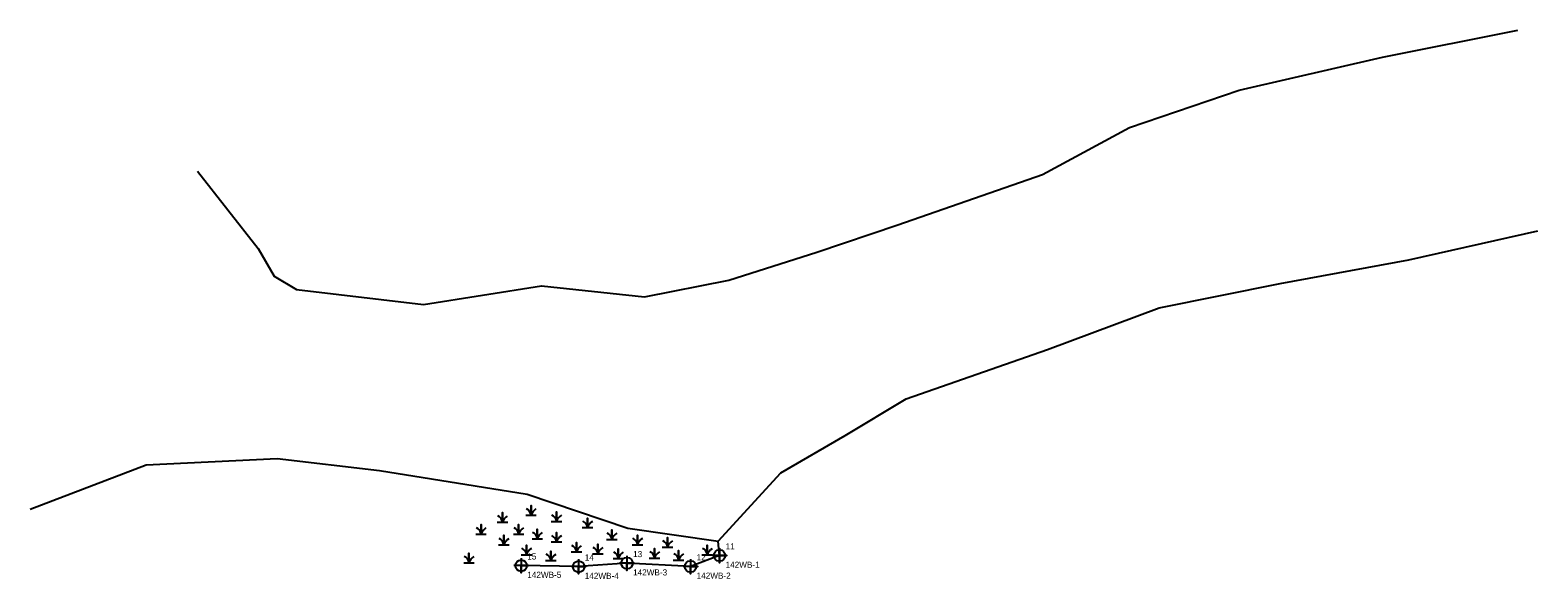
# Model space of a CAD drawing. Extents: x 2110998 to 2111615, y 1005740 to 1005964.
import ezdxf

# ---------------------------------------------------------------- set-up
doc = ezdxf.new("R2010")
doc.units = 0
for name, color, linetype in [('Exist Environmental Wetland Boundary', 7, 'Continuous'), ('Exist Environmental Wetland Boundary Cogo Comment', 7, 'Continuous'), ('Exist Environmental Wetland Boundary Cogo Number', 7, 'Continuous'), ('Exist Environmental Wetland Boundary Cogo Point CELL', 7, 'Continuous'), ('Exist Hydro Jurisdictional Stream or Body of Water Mitigable', 7, 'Continuous'), ('Exist Hydro Swamp or Marsh', 7, 'Continuous')]:
    doc.layers.add(name, color=color, linetype=linetype)

msp = doc.modelspace()

# ---------------------------------------------------------------- linework, layer by layer
at = {"layer": 'Exist Environmental Wetland Boundary'}
msp.add_line((2111279.88, 1005749.38), (2111279.31, 1005755.28), dxfattribs=at)
msp.add_lwpolyline([(2111279.88, 1005749.38), (2111268.04, 1005744.93), (2111242.04, 1005746.25), (2111222.26, 1005744.86), (2111198.75, 1005745.27)], dxfattribs=at)
at = {"layer": 'Exist Environmental Wetland Boundary Cogo Point CELL'}
for points in [[(2111198.75, 1005748.27), (2111198.75, 1005742.27), (2111198.75, 1005745.27), (2111201.75, 1005745.27), (2111195.75, 1005745.27)], [(2111222.26, 1005747.86), (2111222.26, 1005741.86), (2111222.26, 1005744.86), (2111225.26, 1005744.86), (2111219.26, 1005744.86)], [(2111242.04, 1005749.25), (2111242.04, 1005743.25), (2111242.04, 1005746.25), (2111245.04, 1005746.25), (2111239.04, 1005746.25)], [(2111268.04, 1005747.93), (2111268.04, 1005741.93), (2111268.04, 1005744.93), (2111271.04, 1005744.93), (2111265.04, 1005744.93)], [(2111279.88, 1005752.38), (2111279.88, 1005746.38), (2111279.88, 1005749.38), (2111282.88, 1005749.38), (2111276.88, 1005749.38)]]:
    msp.add_lwpolyline(points, dxfattribs=at)
for centre in [(2111242.04, 1005746.25), (2111279.88, 1005749.38), (2111198.75, 1005745.27), (2111222.26, 1005744.86), (2111268.04, 1005744.93)]:
    msp.add_circle(centre, 2.34, dxfattribs=at)
at = {"layer": 'Exist Hydro Jurisdictional Stream or Body of Water Mitigable'}
for points in [[(2111066.33, 1005906.62), (2111091.17, 1005874.98), (2111097.77, 1005863.75), (2111106.81, 1005858.31), (2111158.74, 1005852.11), (2111207.06, 1005859.75), (2111249.26, 1005855.28), (2111283.66, 1005862.06), (2111319.72, 1005873.59), (2111352.86, 1005884.66), (2111412, 1005905.25), (2111447.66, 1005924.6), (2111492.51, 1005939.82), (2111551.13, 1005953.39), (2111606.48, 1005964.38)], [(2110997.88, 1005768.36), (2111045.38, 1005786.58), (2111098.97, 1005789.12), (2111140.82, 1005784.24), (2111201.22, 1005774.47), (2111242.33, 1005760.59), (2111279.31, 1005755.28), (2111304.91, 1005783.21), (2111331.28, 1005798.52), (2111356.24, 1005813.53), (2111414.03, 1005833.75), (2111459.69, 1005850.7), (2111509.19, 1005860.72), (2111561.93, 1005870.46), (2111614.66, 1005882.33)]]:
    msp.add_lwpolyline(points, dxfattribs=at)
at = {"layer": 'Exist Hydro Swamp or Marsh'}
for p, q in [((2111202.8, 1005767.67), (2111202.8, 1005767.67)), ((2111191.08, 1005764.8), (2111191.08, 1005764.8)), ((2111213.19, 1005765.13), (2111213.19, 1005765.13)), ((2111225.89, 1005762.59), (2111225.89, 1005762.59)), ((2111182.35, 1005759.94), (2111182.35, 1005759.94)), ((2111191.64, 1005755.51), (2111191.64, 1005755.51)), ((2111197.71, 1005759.94), (2111197.71, 1005759.94)), ((2111205.34, 1005758.06), (2111205.34, 1005758.06)), ((2111213.19, 1005756.73), (2111213.19, 1005756.73)), ((2111235.84, 1005757.72), (2111235.84, 1005757.72)), ((2111246.34, 1005755.62), (2111246.34, 1005755.62)), ((2111258.61, 1005754.63), (2111258.61, 1005754.63)), ((2111177.38, 1005748.22), (2111177.38, 1005748.22)), ((2111200.92, 1005751.53), (2111200.92, 1005751.53)), ((2111210.86, 1005749.1), (2111210.86, 1005749.1)), ((2111221.36, 1005752.64), (2111221.36, 1005752.64)), ((2111230.09, 1005751.87), (2111230.09, 1005751.87)), ((2111238.49, 1005749.99), (2111238.49, 1005749.99)), ((2111253.3, 1005750.1), (2111253.3, 1005750.1)), ((2111263.14, 1005749.32), (2111263.14, 1005749.32)), ((2111274.85, 1005751.42), (2111274.85, 1005751.42))]:
    msp.add_line(p, q, dxfattribs=at)
for points in [[(2111188.93, 1005763.02), (2111191.08, 1005763.02), (2111191.08, 1005766.96), (2111191.08, 1005763.02), (2111193.23, 1005763.02)], [(2111200.65, 1005765.89), (2111202.8, 1005765.89), (2111202.8, 1005769.84), (2111202.8, 1005765.89), (2111204.95, 1005765.89)], [(2111211.04, 1005763.35), (2111213.19, 1005763.35), (2111213.19, 1005767.29), (2111213.19, 1005763.35), (2111215.34, 1005763.35)], [(2111180.2, 1005758.15), (2111182.35, 1005758.15), (2111182.35, 1005762.1), (2111182.35, 1005758.15), (2111184.5, 1005758.15)], [(2111195.56, 1005758.15), (2111197.71, 1005758.15), (2111197.71, 1005762.1), (2111197.71, 1005758.15), (2111199.86, 1005758.15)], [(2111203.19, 1005756.27), (2111205.34, 1005756.27), (2111205.34, 1005760.22), (2111205.34, 1005756.27), (2111207.49, 1005756.27)], [(2111223.74, 1005760.81), (2111225.89, 1005760.81), (2111225.89, 1005764.75), (2111225.89, 1005760.81), (2111228.05, 1005760.81)], [(2111189.49, 1005753.73), (2111191.64, 1005753.73), (2111191.64, 1005757.68), (2111191.64, 1005753.73), (2111193.79, 1005753.73)], [(2111211.04, 1005754.95), (2111213.19, 1005754.95), (2111213.19, 1005758.89), (2111213.19, 1005754.95), (2111215.34, 1005754.95)], [(2111219.21, 1005750.86), (2111221.36, 1005750.86), (2111221.36, 1005754.8), (2111221.36, 1005750.86), (2111223.51, 1005750.86)], [(2111227.94, 1005750.08), (2111230.09, 1005750.08), (2111230.09, 1005754.03), (2111230.09, 1005750.08), (2111232.24, 1005750.08)], [(2111233.69, 1005755.94), (2111235.84, 1005755.94), (2111235.84, 1005759.89), (2111235.84, 1005755.94), (2111237.99, 1005755.94)], [(2111244.19, 1005753.84), (2111246.34, 1005753.84), (2111246.34, 1005757.79), (2111246.34, 1005753.84), (2111248.49, 1005753.84)], [(2111256.46, 1005752.85), (2111258.61, 1005752.85), (2111258.61, 1005756.79), (2111258.61, 1005752.85), (2111260.76, 1005752.85)], [(2111175.23, 1005746.43), (2111177.38, 1005746.43), (2111177.38, 1005750.38), (2111177.38, 1005746.43), (2111179.53, 1005746.43)], [(2111198.77, 1005749.75), (2111200.92, 1005749.75), (2111200.92, 1005753.7), (2111200.92, 1005749.75), (2111203.07, 1005749.75)], [(2111208.71, 1005747.32), (2111210.87, 1005747.32), (2111210.87, 1005751.26), (2111210.87, 1005747.32), (2111213.02, 1005747.32)], [(2111236.34, 1005748.2), (2111238.49, 1005748.2), (2111238.49, 1005752.15), (2111238.49, 1005748.2), (2111240.64, 1005748.2)], [(2111251.15, 1005748.31), (2111253.3, 1005748.31), (2111253.3, 1005752.26), (2111253.3, 1005748.31), (2111255.45, 1005748.31)], [(2111260.99, 1005747.54), (2111263.14, 1005747.54), (2111263.14, 1005751.48), (2111263.14, 1005747.54), (2111265.29, 1005747.54)], [(2111272.7, 1005749.64), (2111274.85, 1005749.64), (2111274.85, 1005753.59), (2111274.85, 1005749.64), (2111277, 1005749.64)]]:
    msp.add_lwpolyline(points, dxfattribs=at)
for centre, radius, start, end in [((2111199.73, 1005765.67), 3.07, 4.14034, 67.53497), ((2111207.36, 1005764.38), 4.81, 122.12745, 161.62219), ((2111179.29, 1005757.93), 3.07, 4.14034, 67.53497), ((2111186.91, 1005756.64), 4.81, 122.12745, 161.62219), ((2111188.02, 1005762.79), 3.07, 4.14034, 67.53497), ((2111195.64, 1005761.5), 4.81, 122.12745, 161.62219), ((2111194.65, 1005757.93), 3.07, 4.14034, 67.53497), ((2111202.27, 1005756.64), 4.81, 122.12745, 161.62219), ((2111210.12, 1005763.13), 3.07, 4.14034, 67.53497), ((2111217.75, 1005761.83), 4.81, 122.12745, 161.62219), ((2111222.83, 1005760.58), 3.07, 4.14034, 67.53497), ((2111230.46, 1005759.29), 4.81, 122.12745, 161.62219), ((2111188.57, 1005753.51), 3.07, 4.14034, 67.53497), ((2111196.2, 1005752.22), 4.81, 122.12745, 161.62219), ((2111202.27, 1005756.05), 3.07, 4.14034, 67.53497), ((2111209.9, 1005754.76), 4.81, 122.12745, 161.62219), ((2111210.12, 1005754.72), 3.07, 4.14034, 67.53497), ((2111217.75, 1005753.43), 4.81, 122.12745, 161.62219), ((2111232.77, 1005755.72), 3.07, 4.14034, 67.53497), ((2111240.4, 1005754.43), 4.81, 122.12745, 161.62219), ((2111243.27, 1005753.62), 3.07, 4.14034, 67.53497), ((2111250.9, 1005752.33), 4.81, 122.12745, 161.62219), ((2111255.54, 1005752.62), 3.07, 4.14034, 67.53497), ((2111263.17, 1005751.33), 4.81, 122.12745, 161.62219), ((2111174.31, 1005746.21), 3.07, 4.14034, 67.53497), ((2111181.94, 1005744.92), 4.81, 122.12745, 161.62219), ((2111197.85, 1005749.53), 3.07, 4.14034, 67.53497), ((2111205.48, 1005748.24), 4.81, 122.12745, 161.62219), ((2111207.8, 1005747.1), 3.07, 4.14034, 67.53497), ((2111215.43, 1005745.8), 4.81, 122.12745, 161.62219), ((2111218.3, 1005750.63), 3.07, 4.14034, 67.53497), ((2111225.92, 1005749.34), 4.81, 122.12745, 161.62219), ((2111227.03, 1005749.86), 3.07, 4.14034, 67.53497), ((2111234.65, 1005748.57), 4.81, 122.12745, 161.62219), ((2111235.43, 1005747.98), 3.07, 4.14034, 67.53497), ((2111243.05, 1005746.69), 4.81, 122.12745, 161.62219), ((2111250.24, 1005748.09), 3.07, 4.14034, 67.53497), ((2111257.86, 1005746.8), 4.81, 122.12745, 161.62219), ((2111260.07, 1005747.32), 3.07, 4.14034, 67.53497), ((2111267.7, 1005746.02), 4.81, 122.12745, 161.62219), ((2111271.79, 1005749.42), 3.07, 4.14034, 67.53497), ((2111279.41, 1005748.12), 4.81, 122.12745, 161.62219)]:
    msp.add_arc(centre, radius, start, end, dxfattribs=at)

# ---------------------------------------------------------------- texts
at = {"layer": 'Exist Environmental Wetland Boundary Cogo Comment'}
for s, p in [('142WB-5', (2111201.25, 1005740.27)), ('142WB-4', (2111224.76, 1005739.86)), ('142WB-3', (2111244.54, 1005741.25)), ('142WB-2', (2111270.54, 1005739.93)), ('142WB-1', (2111282.38, 1005744.38))]:
    msp.add_text(s, height=2.5, dxfattribs=at).set_placement(p)
at = {"layer": 'Exist Environmental Wetland Boundary Cogo Number'}
for s, p in [('11', (2111282.38, 1005751.88)), ('15', (2111201.25, 1005747.77)), ('14', (2111224.76, 1005747.36)), ('13', (2111244.54, 1005748.75)), ('12', (2111270.54, 1005747.43))]:
    msp.add_text(s, height=2.5, dxfattribs=at).set_placement(p)

doc.saveas('drawing.dxf')
